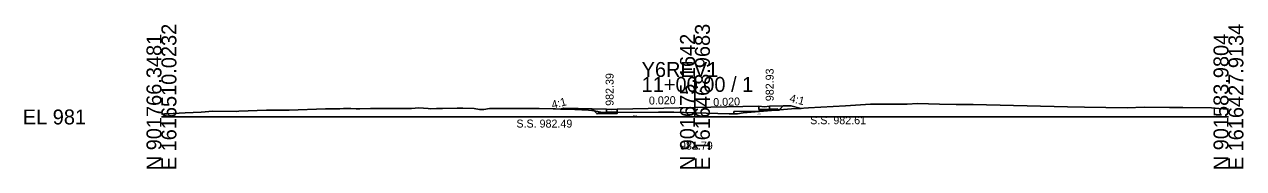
# Model space of a CAD drawing. Extents: x -26 to 203, y -10 to 2517.
# Drawn here: x -25.7 to 202.8, y 990.3 to 1017.4 of the extents above; entities that cross this region are included whole.
import ezdxf

# ---------------------------------------------------------------- set-up
doc = ezdxf.new("R2010")
doc.units = 0
for name, color, linetype in [('Exist Cross Section Cell', 7, 'Continuous'), ('Exist XS Center Line Elevation Label', 7, 'Continuous'), ('Exist XS Ground Line', 7, 'Continuous'), ('Prop XS Dump Level', 7, 'Continuous'), ('Prop XS Earthwork Shape', 7, 'Continuous'), ('Prop XS Finish Grade Earthwork', 7, 'Continuous'), ('Prop XS Finish Grade Pavement', 7, 'Continuous'), ('Prop XS Hydro Elevations', 7, 'Continuous'), ('Prop XS Pvmt Edge Slope', 7, 'Continuous'), ('Prop XS SE Text', 7, 'Continuous'), ('Prop XS Side Slope Text', 7, 'Continuous'), ('Prop XS SS Elevation Text', 7, 'Continuous'), ('Prop XS Subgrade CurbGutter', 7, 'Continuous'), ('Prop XS Subgrade Earthwork', 7, 'Continuous')]:
    doc.layers.add(name, color=color, linetype=linetype)

msp = doc.modelspace()

# ---------------------------------------------------------------- linework, layer by layer
at = {"layer": 'Exist Cross Section Cell'}
for p, q in [((100, 1000), (100, 1007.51)), ((0, 1000), (100, 1000)), ((100, 1000), (200, 1000))]:
    msp.add_line(p, q, dxfattribs=at)
at = {"layer": 'Exist XS Ground Line'}
msp.add_lwpolyline([(0, 1000.55), (0.57, 1000.57), (1.05, 1000.59), (4.42, 1000.77), (7.43, 1000.9), (9.64, 1001.08), (13.99, 1001.04), (14.53, 1001.06), (19.7, 1001.25), (22.5, 1001.27), (23.91, 1001.26), (30.77, 1001.52), (31.26, 1001.52), (31.66, 1001.54), (32.5, 1001.55), (33.46, 1001.54), (34.14, 1001.56), (34.82, 1001.59), (35.48, 1001.59), (36.51, 1001.53), (37.18, 1001.52), (39.17, 1001.56), (41.14, 1001.59), (42.28, 1001.59), (43.18, 1001.61), (45.8, 1001.59), (46.86, 1001.59), (48.26, 1001.72), (49.97, 1001.59), (50.35, 1001.55), (51.57, 1001.59), (52.69, 1001.6), (55.4, 1001.63), (56.52, 1001.67), (58.6, 1001.62), (59.64, 1001.38), (60.41, 1001.39), (61.48, 1001.56), (65.97, 1001.58), (67.21, 1001.59), (70.77, 1001.58), (73.43, 1001.52), (73.89, 1001.52), (75.02, 1001.48), (77.46, 1001.39), (80.04, 1001.3), (80.67, 1001.22), (81.78, 1001.03), (82.62, 1000.84), (82.94, 1000.84), (84.33, 1000.86), (93.14, 1000.91), (95.26, 1000.93), (96.03, 1000.9), (100, 1000.79), (106.42, 1000.6), (107.96, 1000.56), (109.05, 1000.78), (118.09, 1001.54), (119.45, 1001.58), (121.29, 1001.7), (128.2, 1002.11), (132.91, 1002.4), (139.78, 1002.4), (141.71, 1002.5), (145.81, 1002.39), (148.95, 1002.34), (149.92, 1002.34), (152.12, 1002.33), (169.83, 1001.88), (173, 1001.84), (180.99, 1001.74), (184.17, 1001.83), (188.92, 1001.78), (191.42, 1001.8), (196.83, 1001.7), (198.22, 1001.6), (199.03, 1001.54), (200, 1001.47)], dxfattribs=at)
at = {"layer": 'Prop XS Earthwork Shape'}
for points in [[(80.69, 1001.53), (75.4, 1001.64), (74.78, 1001.49), (75.02, 1001.48), (77.46, 1001.39), (80.04, 1001.3), (80.67, 1001.22), (81.08, 1001.15)], [(81.65, 1000.57), (81.08, 1001.15), (81.78, 1001.03), (82.62, 1000.84), (81.9, 1000.83)], [(107.3, 1001), (112, 1001.09), (112, 1001.18), (114.37, 1001.23), (109.05, 1000.78), (107.96, 1000.56), (107.3, 1000.58)], [(114.37, 1001.23), (115.75, 1001.25), (115.67, 1001.33)], [(115.67, 1001.33), (115.85, 1001.35), (115.75, 1001.25)], [(115.85, 1001.35), (116.56, 1002.06), (118, 1002.09), (119.92, 1001.61), (119.45, 1001.58), (118.09, 1001.54)], [(81.9, 1000.83), (81.65, 1000.57), (85.4, 1000.65), (85.4, 1000.9), (84.33, 1000.86), (82.94, 1000.84), (82.62, 1000.84)]]:
    msp.add_lwpolyline(points, close=True, dxfattribs=at)
at = {"layer": 'Prop XS Finish Grade Earthwork'}
for p, q in [((75.4, 1001.64), (74.78, 1001.49)), ((83.4, 1001.48), (75.4, 1001.64)), ((114, 1002.01), (118, 1002.09)), ((118, 1002.09), (119.92, 1001.61))]:
    msp.add_line(p, q, dxfattribs=at)
at = {"layer": 'Prop XS Finish Grade Pavement'}
for q in [(85.4, 1001.48), (112, 1002.01)]:
    msp.add_line((100, 1001.77), q, dxfattribs=at)
at = {"layer": 'Prop XS Pvmt Edge Slope'}
for p, q in [((114.5, 1001.48), (115.5, 1001.5)), ((115.5, 1001.5), (115.75, 1001.25)), ((81.9, 1000.83), (81.65, 1000.57)), ((82.9, 1000.85), (81.9, 1000.83))]:
    msp.add_line(p, q, dxfattribs=at)
at = {"layer": 'Prop XS Subgrade CurbGutter'}
for p, q in [((83.4, 1000.89), (83.4, 1001.48)), ((83.4, 1001.48), (84.41, 1001.39)), ((84.41, 1001.39), (85.4, 1001.48)), ((85.4, 1001.48), (85.4, 1000.9)), ((112, 1002.01), (112, 1001.43)), ((112, 1001.42), (112, 1002.01)), ((112, 1002.01), (113.01, 1001.92)), ((114, 1001.42), (112, 1001.42)), ((113.01, 1001.92), (114, 1002.01)), ((114, 1001.47), (114.5, 1001.48)), ((85.4, 1000.9), (82.9, 1000.85)), ((85.4, 1000.89), (83.4, 1000.89))]:
    msp.add_line(p, q, dxfattribs=at)
for points in [[(83.4, 1000.89), (85.4, 1000.89), (85.4, 1001.48)], [(112, 1001.42), (114, 1001.42), (114, 1002.01)]]:
    msp.add_lwpolyline(points, dxfattribs=at)
at = {"layer": 'Prop XS Subgrade Earthwork'}
for p, q in [((81.65, 1000.57), (80.69, 1001.53)), ((107.3, 1001), (112, 1001.09)), ((107.3, 1001), (107.3, 1000.58)), ((112, 1001.18), (115.75, 1001.25)), ((112, 1001.09), (112, 1001.18)), ((115.75, 1001.25), (116.56, 1002.06)), ((85.4, 1000.65), (81.65, 1000.57)), ((85.4, 1000.87), (85.4, 1000.65))]:
    msp.add_line(p, q, dxfattribs=at)

# ---------------------------------------------------------------- texts
at = {"layer": 'Exist Cross Section Cell'}
for s, p in [('E 1616510.0232', (2.8, 990)), ('E 1616468.9683', (102.8, 990)), ('E 1616427.9134', (202.8, 990)), ('N 901766.3481', (0, 990)), ('N 901675.1642', (100, 990)), ('N 901583.9804', (200, 990))]:
    msp.add_text(s, height=2.8, rotation=90, dxfattribs=at).set_placement(p)
for s, p in [('Y6REV1', (90, 1007.51)), ('11+00.00 / 1', (90, 1004.71)), ('EL 981', (-26, 998.6))]:
    msp.add_text(s, height=2.8, dxfattribs=at).set_placement(p)
at = {"layer": 'Exist XS Center Line Elevation Label'}
msp.add_text('981.79', height=1.5, dxfattribs=at).set_placement((97.2, 993.88))
msp.add_text('981.79', height=1.5, dxfattribs=at).set_placement((97.2, 993.88))
at = {"layer": 'Prop XS Dump Level'}
for p in [(88.44, 1000.06), (111.64, 1000.46)]:
    msp.add_text('Eop', height=0.3, dxfattribs=at).set_placement(p)
at = {"layer": 'Prop XS Hydro Elevations'}
for s, p in [('982.39', (84.75, 1002.09)), ('982.93', (114.75, 1002.96))]:
    msp.add_text(s, height=1.5, rotation=90, dxfattribs=at).set_placement(p)
at = {"layer": 'Prop XS SE Text'}
for rotation, p in [(1.1458, (91.38, 1002.32)), (1.7699, (103.45, 1002.02))]:
    msp.add_text('0.020', height=1.5, rotation=rotation, dxfattribs=at).set_placement(p)
at = {"layer": 'Prop XS Side Slope Text'}
for rotation, p in [(14.0362, (73.32, 1001.54)), (345.9638, (117.62, 1002.87))]:
    msp.add_text('4:1', height=1.5, rotation=rotation, dxfattribs=at).set_placement(p)
at = {"layer": 'Prop XS SS Elevation Text'}
for s, p in [('S.S. 982.49', (66.53, 998.01)), ('S.S. 982.61', (121.59, 998.64))]:
    msp.add_text(s, height=1.5, dxfattribs=at).set_placement(p)

doc.saveas('drawing.dxf')
